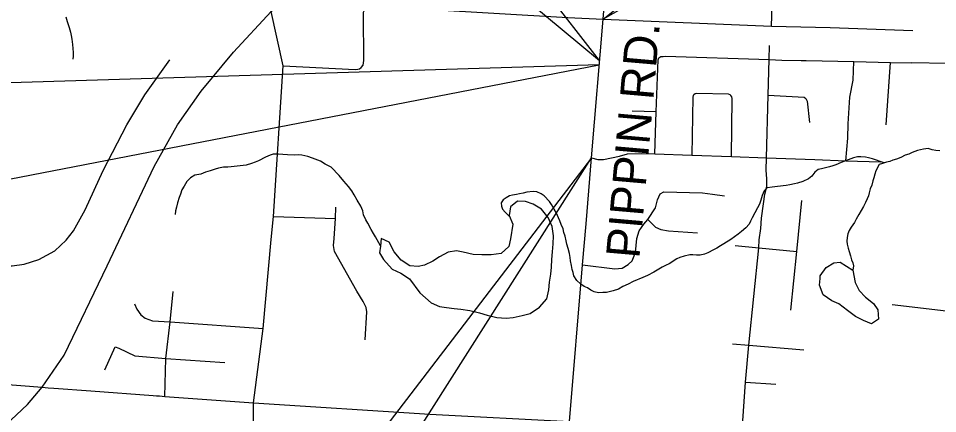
# Model space of a CAD drawing. Extents: x 0 to 69.5, y -4.5 to 22.
# Drawn here: x 4.328 to 5.7, y 18.449 to 19.04 of the extents above; entities that cross this region are included whole.
import ezdxf

# ---------------------------------------------------------------- set-up
doc = ezdxf.new("R2010")
doc.units = 0
for name, color, linetype in [('GM_X_County_Road', 7, 'Continuous'), ('GM_X_County_ROW', 7, 'Continuous'), ('GM_X_Interstate_Route', 7, 'Continuous'), ('GM_X_Minor_Lake', 7, 'Continuous'), ('GM_X_Minor_River', 7, 'Continuous'), ('GM_X_Township_Subdivision', 7, 'Continuous'), ('RD_P_Text', 7, 'Continuous'), ('SH_Data', 7, 'Continuous')]:
    doc.layers.add(name, color=color, linetype=linetype)

msp = doc.modelspace()

# ---------------------------------------------------------------- linework, layer by layer
at = {"layer": 'GM_X_County_Road'}
for points in [[(5.15, 18.4371), (5.1698, 18.6713), (5.1749, 18.7327), (5.1831, 18.831), (5.2002, 19.0384), (5.204, 19.0829), (5.2078, 19.1282), (5.2116, 19.1733), (5.2155, 19.22), (5.2203, 19.2768)], [(4.7231, 18.9689), (4.8302, 18.963), (4.8342, 18.9639), (4.8366, 18.9643), (4.8395, 18.9662), (4.8421, 18.9698), (4.8435, 18.9764), (4.8426, 19.0456), (4.8429, 19.0489), (4.8437, 19.0509), (4.8452, 19.0529), (4.8485, 19.0559), (4.8538, 19.057), (4.8594, 19.057), (4.9353, 19.0534), (5.1475, 19.0408), (5.2002, 19.0384)], [(4.6785, 18.4652), (4.6932, 18.5761), (4.7051, 18.709), (4.7086, 18.7436), (4.7231, 18.9689)], [(4.2176, 18.4999), (4.2674, 18.4962), (4.3632, 18.4884), (4.3722, 18.4877), (4.3808, 18.4871)], [(4.3808, 18.4871), (4.4361, 18.483), (4.5287, 18.4761), (4.5341, 18.4757), (4.5384, 18.4754)], [(4.5384, 18.4754), (4.5461, 18.4748), (4.6785, 18.4652), (4.9418, 18.4482), (5.15, 18.4371), (5.2136, 18.4338), (5.4078, 18.4238), (5.4377, 18.4223), (5.5969, 18.4142)]]:
    msp.add_lwpolyline(points, dxfattribs=at)
at = {"layer": 'GM_X_County_ROW'}
msp.add_lwpolyline([(4.7231, 18.9689), (4.7052, 19.0496), (4.5464, 19.7888)], dxfattribs=at)
at = {"layer": 'GM_X_Interstate_Route'}
for points in [[(4.3688, 18.4966), (4.396, 18.5364), (4.4605, 18.6699), (4.5302, 18.8182), (4.5651, 18.8806), (4.6006, 18.9309), (4.6486, 18.9891), (4.7052, 19.0496), (4.7706, 19.1075), (4.9553, 19.2548), (5.2358, 19.4841)], [(3.7943, 18.0368), (3.8382, 18.0704), (3.8558, 18.0839), (4.1317, 18.2944), (4.2208, 18.3608), (4.3, 18.4242), (4.3415, 18.4627), (4.3632, 18.4884), (4.3688, 18.4966)]]:
    msp.add_lwpolyline(points, dxfattribs=at)
at = {"layer": 'GM_X_Minor_Lake'}
for points in [[(4.9271, 18.6297), (4.9439, 18.6145), (4.9563, 18.609), (4.9666, 18.6076), (4.9779, 18.6062), (4.9878, 18.6053), (5.0014, 18.6031), (5.0158, 18.5994), (5.0275, 18.5961), (5.0418, 18.5924), (5.0559, 18.5917), (5.0661, 18.5927), (5.0795, 18.5954), (5.0917, 18.5986), (5.1056, 18.6082), (5.1165, 18.6206), (5.1194, 18.6342), (5.1204, 18.6452), (5.1222, 18.6573), (5.1235, 18.668), (5.1238, 18.6794), (5.1248, 18.6908), (5.1258, 18.7026), (5.1264, 18.7147), (5.1244, 18.7288), (5.1182, 18.7423), (5.1086, 18.7546), (5.0962, 18.7621), (5.0845, 18.7662), (5.0724, 18.7664), (5.0623, 18.7579), (5.0602, 18.745), (5.0656, 18.7323), (5.0621, 18.7103)], [(5.0621, 18.7103), (5.0596, 18.6986), (5.048, 18.6881), (5.0331, 18.6865), (5.0195, 18.6861), (5.0062, 18.6867), (4.9914, 18.6901), (4.9816, 18.6925), (4.969, 18.6901), (4.9564, 18.6835), (4.9464, 18.6769), (4.9337, 18.6707), (4.9242, 18.669), (4.912, 18.67), (4.8989, 18.6782), (4.8885, 18.691), (4.8809, 18.7052), (4.8692, 18.7108), (4.8682, 18.699), (4.8665, 18.6892), (4.8727, 18.6791), (4.8857, 18.6648), (4.8985, 18.6588), (4.9112, 18.6506), (4.9271, 18.6297)], [(5.524, 18.6511), (5.5241, 18.6549), (5.5331, 18.6672), (5.5447, 18.6742), (5.5542, 18.6755), (5.5731, 18.6635)], [(5.5731, 18.6635), (5.5763, 18.6447), (5.5826, 18.6331), (5.5919, 18.6231), (5.6038, 18.6137), (5.6101, 18.6041), (5.6113, 18.59), (5.6009, 18.5834), (5.5889, 18.5882), (5.5768, 18.5941), (5.5652, 18.6031), (5.5521, 18.6129), (5.5416, 18.6176), (5.5285, 18.6263), (5.5231, 18.6408), (5.524, 18.6511)]]:
    msp.add_lwpolyline(points, dxfattribs=at)
at = {"layer": 'GM_X_Minor_River'}
for points in [[(4.3987, 19.0418), (4.4005, 19.0349), (4.4037, 19.0257), (4.4055, 19.0188), (4.4065, 19.0139), (4.4075, 19.0085), (4.4085, 19.0005), (4.4092, 18.9948), (4.4094, 18.9887), (4.4097, 18.983), (4.4092, 18.9784)], [(4.8683, 18.6999), (4.8634, 18.7085), (4.8608, 18.7131), (4.8579, 18.7181), (4.8542, 18.7242), (4.8491, 18.7338), (4.8462, 18.7385), (4.8429, 18.7458), (4.8419, 18.7519), (4.839, 18.7591), (4.8335, 18.768), (4.8291, 18.7761), (4.8254, 18.7819), (4.8206, 18.7884), (4.8136, 18.7965), (4.8065, 18.8047), (4.7946, 18.8171), (4.7856, 18.8218), (4.7785, 18.8262), (4.7668, 18.8309), (4.7597, 18.8334), (4.7506, 18.8351), (4.746, 18.8355), (4.74, 18.8353), (4.7293, 18.8355), (4.7225, 18.8364), (4.7161, 18.8369), (4.7081, 18.8367), (4.7035, 18.8353), (4.6966, 18.8324), (4.6859, 18.8265), (4.6809, 18.8247), (4.6755, 18.8229), (4.6675, 18.8204), (4.65, 18.8185), (4.6451, 18.8178), (4.6405, 18.8175), (4.6341, 18.8172), (4.6264, 18.8159), (4.6215, 18.8145), (4.6138, 18.8119), (4.607, 18.8098), (4.6001, 18.8069), (4.5913, 18.8052), (4.5844, 18.8015), (4.5793, 18.7959), (4.575, 18.7891), (4.5715, 18.7835), (4.5699, 18.7771), (4.5675, 18.7718), (4.5654, 18.7639), (4.5638, 18.7574), (4.5625, 18.7521), (4.5616, 18.7464)], [(5.6785, 18.8443), (5.6697, 18.8422), (5.6617, 18.8393), (5.6567, 18.8368), (5.6513, 18.835), (5.6448, 18.8317), (5.6383, 18.8292), (5.6326, 18.8277), (5.628, 18.8259), (5.6234, 18.8245), (5.6173, 18.8227), (5.6123, 18.8213), (5.6072, 18.8119), (5.606, 18.807), (5.6043, 18.8013), (5.6027, 18.7968), (5.6011, 18.7903), (5.5991, 18.7847), (5.5974, 18.779), (5.5962, 18.7745), (5.5946, 18.7699), (5.5918, 18.7647), (5.5887, 18.7583), (5.5855, 18.7526), (5.582, 18.7466), (5.578, 18.7395), (5.5753, 18.7346), (5.5706, 18.7274), (5.5674, 18.7226), (5.5654, 18.7176), (5.5646, 18.712), (5.5641, 18.7066), (5.5644, 18.7021), (5.5658, 18.6963), (5.5676, 18.6914), (5.5693, 18.6849), (5.5711, 18.6787), (5.5729, 18.6741), (5.574, 18.6696), (5.5731, 18.6635)], [(5.7027, 18.8416), (5.6967, 18.8424), (5.6914, 18.8433), (5.6853, 18.845), (5.6785, 18.8443)], [(5.6199, 18.8235), (5.6023, 18.8295), (5.5966, 18.8311), (5.5921, 18.832), (5.5849, 18.8329), (5.5799, 18.8326), (5.5742, 18.8312), (5.5623, 18.8269), (5.5558, 18.824), (5.5478, 18.8207), (5.5432, 18.8193), (5.5383, 18.8178), (5.5321, 18.8164), (5.5264, 18.815), (5.5215, 18.814), (5.5165, 18.8099), (5.5118, 18.8039), (5.5068, 18.7998), (5.4983, 18.7958), (5.4903, 18.7933), (5.4857, 18.7926), (5.4789, 18.7909), (5.4735, 18.7898), (5.4606, 18.7886), (5.4526, 18.7876), (5.4454, 18.7862), (5.4407, 18.7817), (5.4379, 18.775), (5.4355, 18.7678), (5.4335, 18.7621), (5.4307, 18.7565), (5.4228, 18.7414), (5.4204, 18.7365), (5.4181, 18.732), (5.4134, 18.7264), (5.4069, 18.7212), (5.4018, 18.7171), (5.391, 18.709), (5.3803, 18.7027), (5.3757, 18.6997), (5.3699, 18.6964), (5.3649, 18.6935), (5.3565, 18.6891), (5.3515, 18.6873), (5.345, 18.6859), (5.3397, 18.686), (5.3344, 18.6865), (5.3298, 18.6862), (5.3215, 18.6845), (5.315, 18.6823), (5.3104, 18.6801), (5.2988, 18.6728), (5.2942, 18.6706), (5.2885, 18.668), (5.2808, 18.6636), (5.2762, 18.6603), (5.2666, 18.6555), (5.2597, 18.6526), (5.2451, 18.6464), (5.2375, 18.6424), (5.2298, 18.6391), (5.2233, 18.6351), (5.2153, 18.6326), (5.2053, 18.6301), (5.2, 18.6298), (5.1936, 18.6296), (5.1871, 18.6312), (5.1819, 18.6336), (5.177, 18.6368), (5.1721, 18.6391), (5.1665, 18.6431), (5.1613, 18.6477), (5.1569, 18.655), (5.1555, 18.66), (5.154, 18.6646), (5.1534, 18.6703), (5.1516, 18.6772), (5.151, 18.6825), (5.15, 18.6883), (5.1482, 18.6959), (5.1464, 18.702), (5.1454, 18.7074), (5.1437, 18.7143), (5.1419, 18.7196), (5.1405, 18.725), (5.1379, 18.7315), (5.1358, 18.7369), (5.134, 18.7418), (5.1307, 18.7484), (5.1274, 18.7545), (5.1234, 18.7615), (5.1204, 18.7661), (5.1122, 18.7742), (5.1077, 18.7774), (5.1013, 18.7805), (5.096, 18.781), (5.0865, 18.7801), (5.0812, 18.7786), (5.0755, 18.7772), (5.0709, 18.7766), (5.0652, 18.7755)], [(5.0652, 18.7755), (5.0606, 18.7745), (5.0556, 18.7716), (5.051, 18.7686), (5.0483, 18.7641), (5.0485, 18.7591), (5.0503, 18.7545), (5.054, 18.7499), (5.0608, 18.7436)]]:
    msp.add_lwpolyline(points, dxfattribs=at)
at = {"layer": 'GM_X_Township_Subdivision'}
for points in [[(5.4518, 19.0279), (5.4531, 19.0743), (5.4539, 19.1197), (5.4546, 19.1585), (5.4547, 19.1612)], [(5.2002, 19.0384), (5.4518, 19.0279), (5.5392, 19.026)], [(5.5392, 19.026), (5.5392, 19.026), (5.6625, 19.0215)], [(5.4078, 18.4238), (5.413, 18.496), (5.4176, 18.5511), (5.4329, 18.6966), (5.4334, 18.7086), (5.4357, 18.7258), (5.4368, 18.7411), (5.4396, 18.7623), (5.4417, 18.7768), (5.4446, 18.7883), (5.4446, 18.7997), (5.4439, 18.813), (5.4443, 18.8311), (5.4466, 18.9246), (5.4479, 18.978), (5.4484, 18.9991)], [(4.2936, 18.6699), (4.3057, 18.6699), (4.3184, 18.6696), (4.3364, 18.6722), (4.3581, 18.6795), (4.3823, 18.6925), (4.3989, 18.7082), (4.4101, 18.7223), (4.4273, 18.7533), (4.4544, 18.8124), (4.4896, 18.8803), (4.5167, 18.9255), (4.5538, 18.9777)], [(5.2774, 18.8371), (5.2797, 18.9), (5.2825, 18.9776), (5.2836, 18.9804), (5.2866, 18.9825), (5.2898, 18.9828), (5.2936, 18.983), (5.4479, 18.978), (5.4671, 18.9773), (5.496, 18.9767), (5.5032, 18.9765)], [(5.5032, 18.9765), (5.5745, 18.9749), (5.6294, 18.9737), (5.6599, 18.973)], [(5.5626, 18.8269), (5.5656, 18.8606), (5.5658, 18.882), (5.5687, 18.922), (5.5735, 18.9474), (5.5745, 18.9749)], [(5.6226, 18.8806), (5.6294, 18.9737)], [(5.7142, 18.9722), (5.6599, 18.973)], [(5.3918, 18.833), (5.3929, 18.9198), (5.3924, 18.9223), (5.3911, 18.9242), (5.3899, 18.9254), (5.3874, 18.9264), (5.3401, 18.9271), (5.3377, 18.9267), (5.3355, 18.9253), (5.3349, 18.9244), (5.3342, 18.922), (5.3327, 18.8351)], [(5.4466, 18.9246), (5.5002, 18.9219), (5.5028, 18.9199), (5.505, 18.9161), (5.5082, 18.884)], [(5.2797, 18.9), (5.2437, 18.9007)], [(5.1831, 18.831), (5.1923, 18.8287), (5.201, 18.8285), (5.2246, 18.8338), (5.2365, 18.8373), (5.2574, 18.8378), (5.2774, 18.8371), (5.3327, 18.8351), (5.3918, 18.833), (5.4443, 18.8311), (5.5164, 18.8286), (5.5164, 18.8286)], [(5.5164, 18.8286), (5.5626, 18.8269), (5.6148, 18.8251)], [(5.1698, 18.6713), (5.2179, 18.6656), (5.2289, 18.6665), (5.2377, 18.672), (5.2436, 18.6773), (5.2485, 18.6899), (5.2507, 18.7109), (5.254, 18.7221), (5.2611, 18.732), (5.2671, 18.7391), (5.2785, 18.7563), (5.2814, 18.7685), (5.2855, 18.7775), (5.2912, 18.7805), (5.3488, 18.7789), (5.3638, 18.7768), (5.3817, 18.7746)], [(5.4807, 18.6038), (5.4892, 18.6913), (5.497, 18.7674)], [(4.8453, 18.5592), (4.8477, 18.6011), (4.8468, 18.6076), (4.8424, 18.6168), (4.833, 18.6319), (4.7997, 18.6913), (4.7979, 18.7003), (4.7989, 18.7106), (4.801, 18.7407), (4.8015, 18.7574)], [(4.7086, 18.7436), (4.801, 18.7407)], [(5.2671, 18.7391), (5.2787, 18.7276), (5.2865, 18.7243), (5.2978, 18.7221), (5.3413, 18.7192)], [(5.3973, 18.7003), (5.4329, 18.6966), (5.4892, 18.6913)], [(4.5461, 18.4748), (4.548, 18.5316), (4.5541, 18.5864), (4.5589, 18.6315)], [(4.501, 18.6129), (4.5046, 18.6051), (4.5105, 18.5964), (4.517, 18.5916), (4.5277, 18.5878), (4.5541, 18.5864), (4.6932, 18.5761)], [(5.9496, 18.5742), (5.6318, 18.6117)], [(4.4568, 18.5147), (4.4722, 18.5486), (4.4776, 18.5468), (4.5015, 18.5352), (4.548, 18.5316), (4.6359, 18.5252)], [(5.3935, 18.5532), (5.4176, 18.5511), (5.5001, 18.5442)], [(5.413, 18.496), (5.458, 18.4931)], [(4.5988, 18.2574), (4.6127, 18.2616), (4.648, 18.2766), (4.6584, 18.284), (4.6645, 18.2929), (4.6683, 18.3047), (4.6704, 18.3186), (4.6751, 18.3717), (4.6785, 18.4006), (4.6785, 18.4652)]]:
    msp.add_lwpolyline(points, dxfattribs=at)
at = {"layer": 'RD_P_Text'}
for points in [[(5.8549, 19.4106), (5.2002, 19.0384), (5.8549, 19.5598), (5.8549, 19.4106)], [(4.8665, 19.2501), (5.1951, 18.9768), (4.8665, 19.3993), (4.8665, 19.2501)], [(4.2827, 18.7932), (5.1946, 18.9704), (4.2827, 18.9424), (4.2827, 18.7932)], [(4.6261, 17.9532), (5.1831, 18.831), (4.6261, 18.1024), (4.6261, 17.9532)]]:
    msp.add_lwpolyline(points, dxfattribs=at)
at = {"layer": 'SH_Data'}
msp.add_line((5.1831, 18.831), (5.2002, 19.0384), dxfattribs=at)

# ---------------------------------------------------------------- texts
at = {"layer": 'RD_P_Text'}
msp.add_text('PIPPIN RD.', height=0.05, rotation=85, dxfattribs=at).set_placement((5.2544, 18.6799))

doc.saveas('drawing.dxf')
